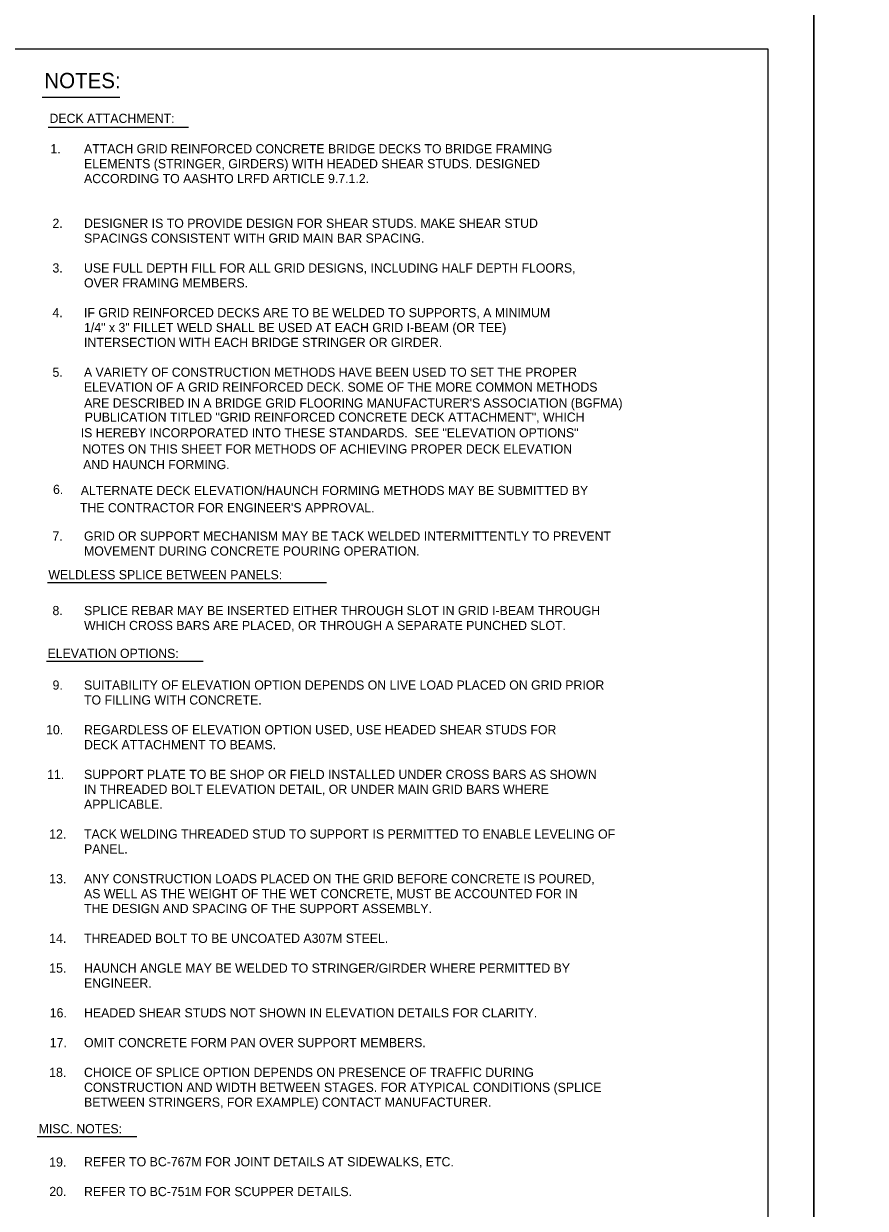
# Model space of a CAD drawing. Extents: x -24512 to -22484, y 4569 to 6351.
# Drawn here: x -23596.4 to -23322, y 5362.6 to 5748.8 of the extents above; entities that cross this region are included whole.
import ezdxf

# ---------------------------------------------------------------- set-up
doc = ezdxf.new("R2010")
doc.units = 0
for name, color, linetype in [('10', 7, 'Continuous'), ('2', 7, 'Continuous'), ('9', 7, 'Continuous'), ('PLT-BNDY', 7, 'Continuous')]:
    doc.layers.add(name, color=color, linetype=linetype)

msp = doc.modelspace()

# ---------------------------------------------------------------- linework, layer by layer
at = {"layer": '10'}
msp.add_line((-23590.38, 5724.86), (-23565, 5724.86), dxfattribs=at)
at = {"layer": '2'}
for p, q in [((-24137.79, 5740.63), (-23353.75, 5740.63)), ((-23353.75, 5740.63), (-23353.75, 5178.04))]:
    msp.add_line(p, q, dxfattribs=at)
at = {"layer": '9'}
for points in [[(-23588.44, 5715.09), (-23542.62, 5715.09)], [(-23588.58, 5566.62), (-23497.62, 5566.62)], [(-23589.01, 5541.01), (-23537.88, 5541.01)], [(-23591.96, 5386), (-23559.46, 5386)]]:
    msp.add_lwpolyline(points, dxfattribs=at)
at = {"layer": 'PLT-BNDY'}
for points in [[(-24179.75, 5757.04), (-23338.75, 5757.04), (-23338.75, 5163.04), (-24179.75, 5163.04)], [(-23338.75, 5757.04), (-22497.75, 5757.04), (-22497.75, 5163.04), (-23338.75, 5163.04)]]:
    msp.add_lwpolyline(points, close=True, dxfattribs=at)

# ---------------------------------------------------------------- texts
at = {"layer": '10'}
msp.add_text('NOTES:', height=5, dxfattribs=at).set_placement((-23589.66, 5727.8))
at = {"layer": '9'}
for s, height, p in [('DECK ATTACHMENT:', 2.9999, (-23587.98, 5716.49)), ('1.', 3, (-23587.69, 5706.56)), ('ATTACH GRID REINFORCED CONCRETE BRIDGE DECKS TO BRIDGE FRAMING', 2.9999, (-23576.72, 5706.56)), ('ELEMENTS (STRINGER, GIRDERS) WITH HEADED SHEAR STUDS. DESIGNED', 2.9999, (-23576.72, 5701.7)), ('ACCORDING TO AASHTO LRFD ARTICLE 9.7.1.2.', 2.9999, (-23576.72, 5696.85)), ('2.', 3, (-23587, 5682.28)), ('DESIGNER IS TO PROVIDE DESIGN FOR SHEAR STUDS. MAKE SHEAR STUD', 2.9999, (-23576.72, 5682.28)), ('SPACINGS CONSISTENT WITH GRID MAIN BAR SPACING.', 2.9999, (-23576.72, 5677.42)), ('3.', 3, (-23587, 5667.71)), ('USE FULL DEPTH FILL FOR ALL GRID DESIGNS, INCLUDING HALF DEPTH FLOORS,  ', 2.9999, (-23576.72, 5667.71)), ('OVER FRAMING MEMBERS. ', 2.9999, (-23576.72, 5662.85)), ('4.', 3, (-23587, 5653.13)), ('IF GRID REINFORCED DECKS ARE TO BE WELDED TO SUPPORTS, A MINIMUM', 2.9999, (-23576.72, 5653.13)), ('1/4" x 3" FILLET WELD SHALL BE USED AT EACH GRID I-BEAM (OR TEE) ', 2.9999, (-23576.72, 5648.28)), ('INTERSECTION WITH EACH BRIDGE STRINGER OR GIRDER. ', 2.9999, (-23576.72, 5643.42)), ('5.', 2.989, (-23586.99, 5633.71)), ('A VARIETY OF CONSTRUCTION METHODS HAVE BEEN USED TO SET THE PROPER ', 2.9892, (-23576.74, 5633.71)), ('ELEVATION OF A GRID REINFORCED DECK. SOME OF THE MORE COMMON METHODS ', 2.9892, (-23576.74, 5628.87)), ("ARE DESCRIBED IN A BRIDGE GRID FLOORING MANUFACTURER'S ASSOCIATION (BGFMA)", 2.9895, (-23576.69, 5623.68)), ('PUBLICATION TITLED "GRID REINFORCED CONCRETE DECK ATTACHMENT", WHICH', 2.9894, (-23576.48, 5619.07)), ('IS HEREBY INCORPORATED INTO THESE STANDARDS.  SEE "ELEVATION OPTIONS"', 2.9894, (-23577.79, 5613.97)), ('NOTES ON THIS SHEET FOR METHODS OF ACHIEVING PROPER DECK ELEVATION', 2.9895, (-23577.26, 5608.7)), ('AND HAUNCH FORMING. ', 2.9894, (-23577, 5603.6)), ('6.', 2.989, (-23586.82, 5595.51)), ('ALTERNATE DECK ELEVATION/HAUNCH FORMING METHODS MAY BE SUBMITTED BY ', 2.9892, (-23577.78, 5595.16)), ("THE CONTRACTOR FOR ENGINEER'S APPROVAL.", 2.9892, (-23578.04, 5589.54)), ('7.', 3, (-23587, 5580.28)), ('GRID OR SUPPORT MECHANISM MAY BE TACK WELDED INTERMITTENTLY TO PREVENT ', 2.9999, (-23576.72, 5580.28)), ('MOVEMENT DURING CONCRETE POURING OPERATION.', 2.9999, (-23576.72, 5575.42)), ('WELDLESS SPLICE BETWEEN PANELS:', 2.9999, (-23588.34, 5567.69)), ('8.', 3, (-23587, 5556)), ('SPLICE REBAR MAY BE INSERTED EITHER THROUGH SLOT IN GRID I-BEAM THROUGH ', 2.9999, (-23576.72, 5556)), ('WHICH CROSS BARS ARE PLACED, OR THROUGH A SEPARATE PUNCHED SLOT.', 2.9999, (-23576.72, 5551.14)), ('ELEVATION OPTIONS:', 2.9999, (-23588.63, 5542.04)), ('9.', 3, (-23586.98, 5531.71)), ('SUITABILITY OF ELEVATION OPTION DEPENDS ON LIVE LOAD PLACED ON GRID PRIOR ', 2.9999, (-23576.72, 5531.71)), ('TO FILLING WITH CONCRETE.', 2.9999, (-23576.72, 5526.85)), ('10.', 3, (-23589.09, 5517.14)), ('REGARDLESS OF ELEVATION OPTION USED, USE HEADED SHEAR STUDS FOR', 2.9999, (-23576.72, 5517.14)), ('DECK ATTACHMENT TO BEAMS.', 2.9999, (-23576.72, 5512.28)), ('11.', 3, (-23588.75, 5502.57)), ('SUPPORT PLATE TO BE SHOP OR FIELD INSTALLED UNDER CROSS BARS AS SHOWN ', 2.9999, (-23576.72, 5502.57)), ('IN THREADED BOLT ELEVATION DETAIL, OR UNDER MAIN GRID BARS WHERE ', 2.9999, (-23576.72, 5497.71)), ('APPLICABLE.', 2.9999, (-23576.72, 5492.86)), ('12.', 3, (-23588.07, 5483.14)), ('TACK WELDING THREADED STUD TO SUPPORT IS PERMITTED TO ENABLE LEVELING OF ', 2.9999, (-23576.72, 5483.14)), ('PANEL.', 3, (-23576.72, 5478.28)), ('13.', 3, (-23588.07, 5468.57)), ('ANY CONSTRUCTION LOADS PLACED ON THE GRID BEFORE CONCRETE IS POURED, ', 2.9999, (-23576.72, 5468.57)), ('AS WELL AS THE WEIGHT OF THE WET CONCRETE, MUST BE ACCOUNTED FOR IN ', 2.9999, (-23576.72, 5463.71)), ('THE DESIGN AND SPACING OF THE SUPPORT ASSEMBLY.', 2.9999, (-23576.72, 5458.86)), ('14.', 3, (-23588.07, 5449.14)), ('THREADED BOLT TO BE UNCOATED A307M STEEL.', 2.9999, (-23576.72, 5449.14)), ('15.', 3, (-23588.07, 5439.43)), ('HAUNCH ANGLE MAY BE WELDED TO STRINGER/GIRDER WHERE PERMITTED BY ', 2.9999, (-23576.72, 5439.43)), ('ENGINEER.', 3, (-23576.72, 5434.57)), ('16.', 3, (-23587.9, 5424.86)), ('HEADED SHEAR STUDS NOT SHOWN IN ELEVATION DETAILS FOR CLARITY.', 2.9999, (-23576.72, 5424.86)), ('17.', 3, (-23587.9, 5415.14)), ('OMIT CONCRETE FORM PAN OVER SUPPORT MEMBERS.', 2.9999, (-23576.72, 5415.14)), ('18.', 3, (-23588.07, 5405.43)), ('CHOICE OF SPLICE OPTION DEPENDS ON PRESENCE OF TRAFFIC DURING ', 2.9999, (-23576.72, 5405.43)), ('CONSTRUCTION AND WIDTH BETWEEN STAGES. FOR ATYPICAL CONDITIONS (SPLICE ', 2.9999, (-23576.72, 5400.57)), ('BETWEEN STRINGERS, FOR EXAMPLE) CONTACT MANUFACTURER.', 2.9999, (-23576.72, 5395.71)), ('MISC. NOTES:', 2.9999, (-23591.5, 5387.05)), ('19.', 3, (-23588.07, 5376.19)), ('REFER TO BC-767M FOR JOINT DETAILS AT SIDEWALKS, ETC.', 2.9999, (-23576.72, 5376.29)), ('20.', 3, (-23588.04, 5366.6)), ('REFER TO BC-751M FOR SCUPPER DETAILS.', 2.9999, (-23576.72, 5366.57))]:
    msp.add_text(s, height=height, dxfattribs=at).set_placement(p)

doc.saveas('drawing.dxf')
